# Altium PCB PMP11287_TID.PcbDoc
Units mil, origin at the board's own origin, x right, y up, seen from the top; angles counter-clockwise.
Board outline 2362.2 x 787.4 mil, 2 copper layers (Top Layer, Bottom Layer), stack 62 mil thick; 39 components, 23 nets, 88 pads, 34 vias.
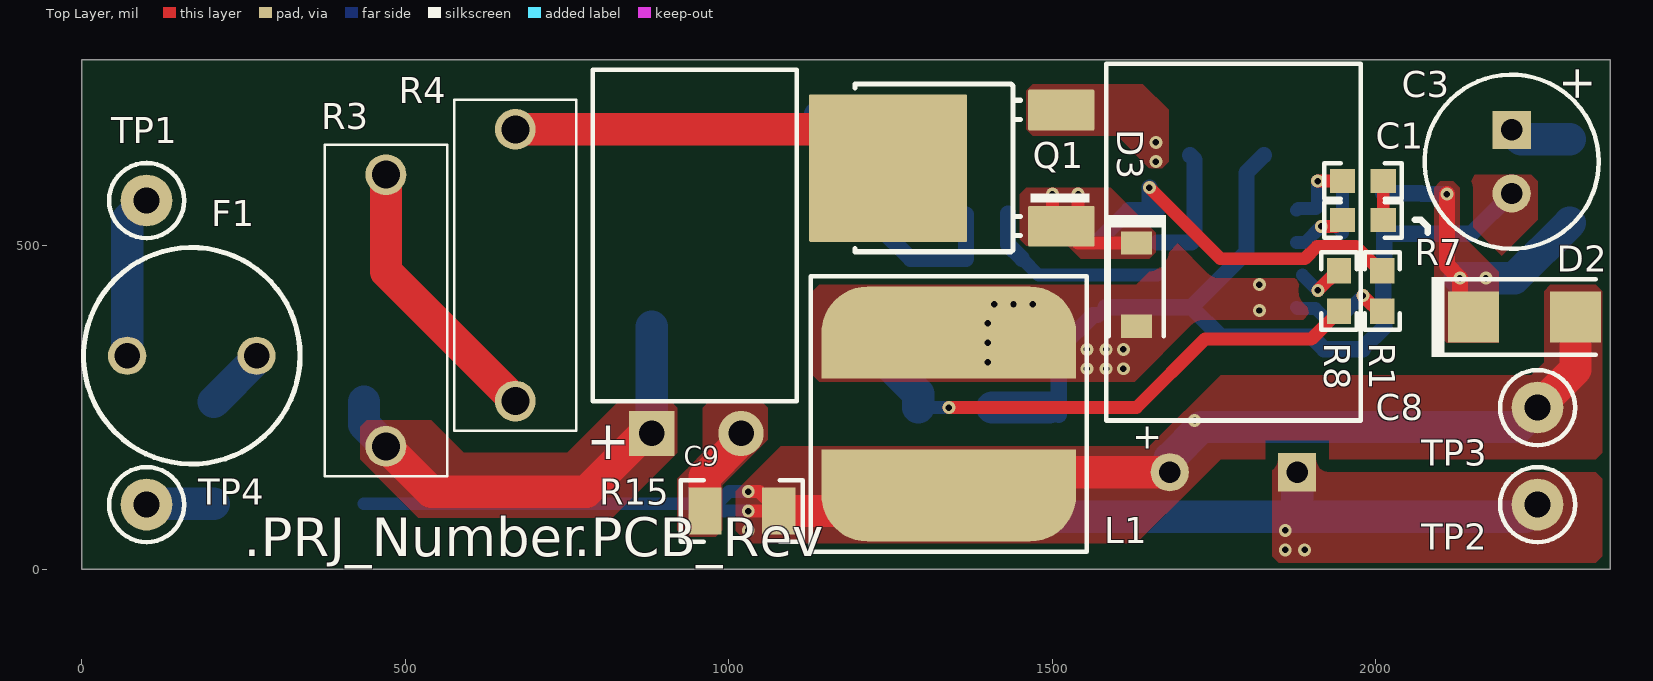
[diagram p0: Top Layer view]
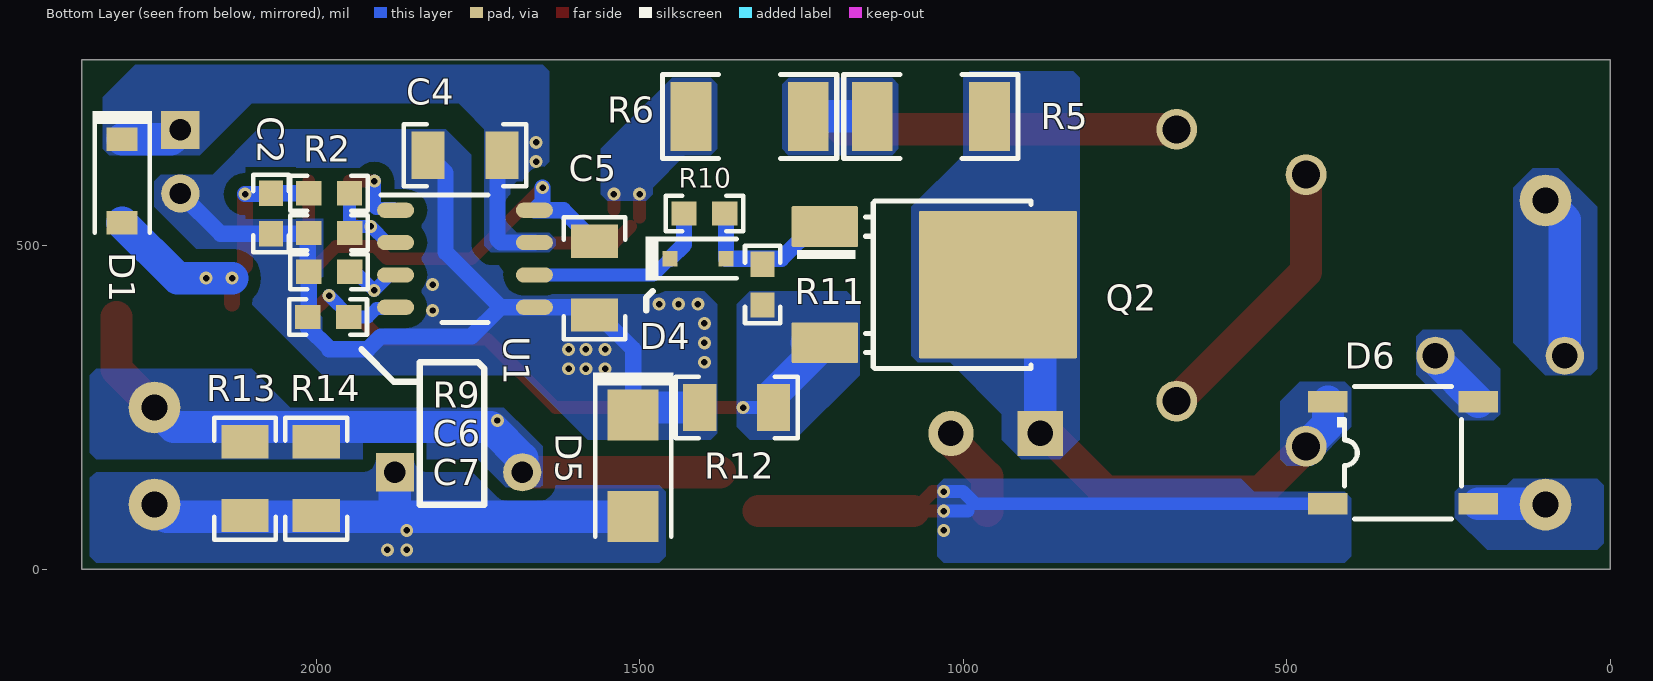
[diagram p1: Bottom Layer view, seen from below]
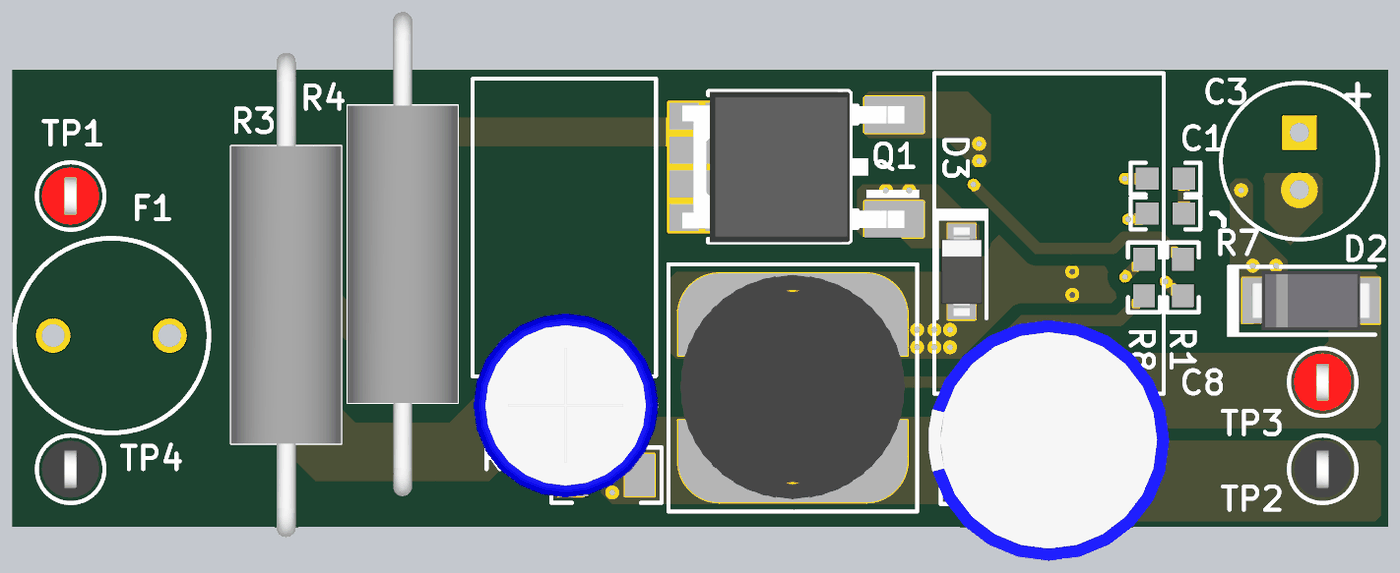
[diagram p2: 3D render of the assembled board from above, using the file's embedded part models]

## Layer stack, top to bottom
Top Solder: solder mask 0.4, Solder Resist, Dk 3.5
Top Layer: signal copper 1.4
Dielectric1: core 59.2, FR-4, Dk 4.8
Bottom Layer: signal copper 1.4
Bottom Solder: solder mask 0.4, Solder Resist, Dk 3.5

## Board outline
0,0 2362.2,0 2362.2,787.4 0,787.4

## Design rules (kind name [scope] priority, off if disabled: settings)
AcuteAngle [All] p1: minimum=4.50000000000000E+0001 checktracksonly=FALSE
AssemblyTestPointUsage [All] p1: valid=2
Clearance Clearance_1 [InNetClass('HV') vs InNet('GND')] p1: gap=60 ignorepadtopadclearanceinfootprint=FALSE except(0: Arc-Hole Track-Hole SMDPad-Hole THPad-Hole Via-Hole Fill-Hole Poly-Hole Region-Hole Text-Hole)
Clearance Clearance_Keepouts [((IsTrack Or IsArc) And Not InPoly) And IsFree and IsKeepOut vs ((IsTrack Or IsArc) And Not InPoly) And IsFree and IsKeepOut] p2: gap=0 ignorepadtopadclearanceinfootprint=FALSE
Clearance Clearance_BoardEdge_MountingHoles [OnCopper and InComponentClass('Mounting Holes') vs IsKeepOut] p3: gap=40 ignorepadtopadclearanceinfootprint=FALSE except(0: Arc-Hole Track-Hole SMDPad-Hole THPad-Hole Via-Hole Fill-Hole Poly-Hole Region-Hole Text-Hole)
Clearance Clearance_BoardEdge_Poly [OnCopper and InPoly vs IsKeepOut] p4: gap=25 ignorepadtopadclearanceinfootprint=FALSE except(0: Arc-Hole Track-Hole SMDPad-Hole THPad-Hole Via-Hole Fill-Hole Poly-Hole Region-Hole Text-Hole)
Clearance Clearance_BoardEdge [OnCopper and Not InComponentClass('Logo') and not InComponentClass('FiducialMark') and not InRegion(1000,500,4000,800) and Not IsKeepout vs IsKeepOut] p5: gap=75 ignorepadtopadclearanceinfootprint=FALSE except(0: Arc-Hole Track-Hole SMDPad-Hole THPad-Hole Via-Hole Fill-Hole Poly-Hole Region-Hole Text-Hole)
Clearance Clearance_Poly [InPolygon] p6: gap=20 ignorepadtopadclearanceinfootprint=FALSE except(0: Arc-Hole Track-Hole SMDPad-Hole THPad-Hole Via-Hole Fill-Hole Poly-Hole Region-Hole Text-Hole)
Clearance [All] p7: gap=7.87 ignorepadtopadclearanceinfootprint=FALSE except(0: Arc-Hole Track-Hole SMDPad-Hole THPad-Hole Via-Hole Fill-Hole Poly-Hole Region-Hole Text-Hole)
ComponentClearance ComponentClearance_MountingHoles_FiducialMarks [InComponentClass('Mounting Holes') vs InComponentClass('FiducialMark')] p1: gap=20 collisioncheckmode=3 verticalgap=10 showdistances=FALSE
ComponentClearance ComponentClearance_Shunt [InComponentClass('Header') vs InComponentClass('Shunt')] p2: gap=0 collisioncheckmode=3 verticalgap=0 showdistances=FALSE
ComponentClearance ComponentClearance_Logo [InComponentClass('Logo')] p3: gap=5 collisioncheckmode=3 verticalgap=10 showdistances=FALSE
ComponentClearance ComponentClearance_ScrewToNut [(HasFootprint('NY PMS 440 0025 PH')) vs (HasFootprint('Keystone_1902C'))] p4: gap=20 collisioncheckmode=3 verticalgap=100000 showdistances=FALSE
ComponentClearance ComponentClearance_MountingHoles [InComponentClass('Mounting Holes')] p5: gap=20 collisioncheckmode=3 verticalgap=10 showdistances=FALSE
ComponentClearance ComponentClearance_SmallPassives [HasFootprint('0201*') or HasFootprint('0402*') or HasFootprint('0508') or HasFootprint('0603*') or HasFootprint('0612') or HasFootprint('0805*') or HasFootprint('0815*') or HasFootprint('0830*') or HasFootprint('1206*') or HasFootprint('1210*') or HasFootprint('1808*') or HasFootprint('1812*') or HasFootprint('1825*') or HasFootprint('2010*') or HasFootprint('2220*') or HasFootprint('2225*') or HasFootprint('2512*') or HasFootprint('2728*') or HasFootprint('3518*') vs HasFootprint('0201*') or HasFootprint('0402*') or HasFootprint('0508') or HasFootprint('0603*') or HasFootprint('0612') or HasFootprint('0805*') or HasFootprint('0815*') or HasFootprint('0830*') or HasFootprint('1206*') or HasFootprint('1210*') or HasFootprint('1808*') or HasFootprint('1812*') or HasFootprint('1825*') or HasFootprint('2010*') or HasFootprint('2220*') or HasFootprint('2225*') or HasFootprint('2512*') or HasFootprint('2728*') or HasFootprint('3518*')] p6: gap=20 collisioncheckmode=3 verticalgap=20 showdistances=FALSE
ComponentClearance ComponentClearance_THtoSMT [IsThruComponent vs IsSMTComponent] p7: gap=10 collisioncheckmode=3 verticalgap=10 showdistances=FALSE
ComponentClearance ComponentClearance_THtoTH [IsThruComponent vs IsThruComponent] p8: gap=10 collisioncheckmode=3 verticalgap=10 showdistances=FALSE
ComponentClearance [All] p9: gap=10 collisioncheckmode=3 verticalgap=10 showdistances=FALSE
DiffPairsRouting [All] p1: maxlimit=100 minlimit=10 mostfreqgap=10 toplayer_minwidth=15 toplayer_maxwidth=15 toplayer_prefwidth=15 bottomlayer_minwidth=15 bottomlayer_maxwidth=15 bottomlayer_prefwidth=15 maxuncoupledlength=1000
FabricationTestPointUsage TestPointUsage [All] p1: valid=2 allowmultiple=FALSE
FabricationTestpoint Testpoint [All] p1: side=3 testpointundercomponent=TRUE minsize=40 maxsize=100 preferedsize=60 minholesize=0 maxholesize=40 preferedholesize=32 testpointgrid=1 allowsidetop=TRUE allowsidebottom=TRUE usegrid=TRUE gridtolerance=0.01
FanoutControl Fanout_LCC [IsLCC] p1: bgadir=Out bgaviamode=Centered fanoutstyle=Auto fanoutdirection=Alternating viagrid=1 // Fanout_LCC (Default Rule)
FanoutControl Fanout_BGA [IsBGA] p2: bgadir=Out bgaviamode=Centered fanoutstyle=Auto fanoutdirection=Alternating viagrid=1 // Fanout_BGA (Default Rule)
FanoutControl Fanout_Default [All] p4: bgadir=Out bgaviamode=Centered fanoutstyle=Auto fanoutdirection=Alternating viagrid=1 // Fanout_Default (Default Rule)
FanoutControl Fanout_Small [(CompPinCount < 5)] p5: bgadir=Out bgaviamode=Centered fanoutstyle=Auto fanoutdirection=OutThenIn viagrid=1 // Fanout_Small (Default Rule)
Height [All] p1: minheight=0 maxheight=3000 prefheight=500
HoleSize [All] p1: absolutevalues=TRUE maxlimit=251 minlimit=7 maxpercent=80.000 minpercent=20.000
MinimumAnnularRing MinimumAnnularRing_ThermalPadVias [IsVia and InAnyComponent] p1: minimumring=5.91
MinimumAnnularRing [All] p2: minimumring=5
MinimumSolderMaskSliver MinimumSolderMaskSliver_Logo [InComponentClass('Logo') vs InComponentClass('Logo')] p1: minsoldermaskwidth=0.7
MinimumSolderMaskSliver [All] p2: minsoldermaskwidth=2
PlaneConnect [All] p1: planeconnectstyle=Relief reliefexpansion=10 reliefentries=4 reliefconductorwidth=10 reliefairgap=10
PolygonConnect PolygonConnect_10 [All vs IsNamedPolygon('D6_3') Or  IsNamedPolygon('F1_2') Or  IsNamedPolygon('R5_1') Or  IsNamedPolygon('D6_4') Or  IsNamedPolygon('CS') Or  IsNamedPolygon('12V') Or  IsNamedPolygon('C9_1') Or  IsNamedPolygon('C3_1') Or  IsNamedPolygon('12V') Or  IsNamedPolygon('C3_1') Or  IsNamedPolygon('C9_2') Or  IsNamedPolygon('12V') Or  IsNamedPolygon('12V') Or  IsNamedPolygon('SW') Or  IsNamedPolygon('D3_1') Or  IsNamedPolygon('C3_1') Or  IsNamedPolygon('C2_1') Or  IsNamedPolygon('C9_1') Or  IsNamedPolygon('SW') Or  IsNamedPolygon('D3_1') Or  IsNamedPolygon('C9_1')] p1: connectstyle=Direct reliefconductorwidth=10 reliefentries=4 polygonreliefangle="90 Angle" airgapwidth=10
PolygonConnect PolygonConnect_9 [All vs IsNamedPolygon('C9_1') Or  IsNamedPolygon('D3_1') Or  IsNamedPolygon('C9_1') Or  IsNamedPolygon('CS') Or  IsNamedPolygon('C3_1') Or  IsNamedPolygon('C9_1') Or  IsNamedPolygon('R5_1') Or  IsNamedPolygon('D3_1') Or  IsNamedPolygon('C3_1') Or  IsNamedPolygon('D6_4') Or  IsNamedPolygon('D6_3') Or  IsNamedPolygon('F1_2') Or  IsNamedPolygon('C3_1') Or  IsNamedPolygon('C2_1') Or  IsNamedPolygon('SW')] p2: connectstyle=Direct reliefconductorwidth=10 reliefentries=4 polygonreliefangle="90 Angle" airgapwidth=10
PolygonConnect PolygonConnect_8 [All vs IsNamedPolygon('D6_3') Or  IsNamedPolygon('C9_1') Or  IsNamedPolygon('R5_1') Or  IsNamedPolygon('C3_1') Or  IsNamedPolygon('F1_2') Or  IsNamedPolygon('C9_1') Or  IsNamedPolygon('D6_4') Or  IsNamedPolygon('D3_1') Or  IsNamedPolygon('CS') Or  IsNamedPolygon('C9_1')] p3: connectstyle=Direct reliefconductorwidth=10 reliefentries=4 polygonreliefangle="90 Angle" airgapwidth=10
PolygonConnect PolygonConnect_7 [All vs IsNamedPolygon('C9_1') Or  IsNamedPolygon('CS') Or  IsNamedPolygon('F1_2') Or  IsNamedPolygon('R5_1') Or  IsNamedPolygon('D6_4') Or  IsNamedPolygon('C9_1') Or  IsNamedPolygon('C9_1') Or  IsNamedPolygon('D6_3')] p4: connectstyle=Direct reliefconductorwidth=10 reliefentries=4 polygonreliefangle="90 Angle" airgapwidth=10
PolygonConnect PolygonConnect_6 [All vs IsNamedPolygon('GND2') Or  IsNamedPolygon('SGND') Or  IsNamedPolygon('GND1') Or  IsNamedPolygon('C901_1') Or  IsNamedPolygon('SGND') Or  IsNamedPolygon('GND2') Or  IsNamedPolygon('GND1')] p5: connectstyle=Direct reliefconductorwidth=10 reliefentries=4 polygonreliefangle="90 Angle" airgapwidth=10
PolygonConnect PolygonConnect_5 [All vs IsNamedPolygon('GND1') Or  IsNamedPolygon('GND1')] p6: connectstyle=Direct reliefconductorwidth=10 reliefentries=4 polygonreliefangle="90 Angle" airgapwidth=10
PolygonConnect PolygonConnect_4 [All vs IsNamedPolygon('C21_1') Or  IsNamedPolygon('C5_1') Or  IsNamedPolygon('C12_2') Or  IsNamedPolygon('C2_2') Or  IsNamedPolygon('C13_1') Or  IsNamedPolygon('C28_1') Or  IsNamedPolygon('C6_1') Or  IsNamedPolygon('GND') Or  IsNamedPolygon('GND2') Or  IsNamedPolygon('C14_1') Or  IsNamedPolygon('C13_1') Or  IsNamedPolygon('Q1_3') Or  IsNamedPolygon('C14_1') Or  IsNamedPolygon('C5_1') Or  IsNamedPolygon('GND2') Or  IsNamedPolygon('C28_1') Or  IsNamedPolygon('D5_2') Or  IsNamedPolygon('D6_2') Or  IsNamedPolygon('D2_1') Or  IsNamedPolygon('C12_2') Or  IsNamedPolygon('D2_1') Or  IsNamedPolygon('C4_1') Or  IsNamedPolygon('C4_1') Or  IsNamedPolygon('C2_2') Or  IsNamedPolygon('GND') Or  IsNamedPolygon('C33_1') Or  IsNamedPolygon('C9_1')] p7: connectstyle=Direct reliefconductorwidth=10 reliefentries=4 polygonreliefangle="90 Angle" airgapwidth=10
PolygonConnect PolygonConnect_3 [All vs IsNamedPolygon('C28_1') Or  IsNamedPolygon('C12_2') Or  IsNamedPolygon('C28_1') Or  IsNamedPolygon('C9_1') Or  IsNamedPolygon('D5_2') Or  IsNamedPolygon('C12_2') Or  IsNamedPolygon('C2_2') Or  IsNamedPolygon('C14_1') Or  IsNamedPolygon('C4_1') Or  IsNamedPolygon('C14_1') Or  IsNamedPolygon('D6_2') Or  IsNamedPolygon('GND2') Or  IsNamedPolygon('Q1_3') Or  IsNamedPolygon('C5_1') Or  IsNamedPolygon('D2_1') Or  IsNamedPolygon('C4_1') Or  IsNamedPolygon('C13_1') Or  IsNamedPolygon('C5_1') Or  IsNamedPolygon('C13_1') Or  IsNamedPolygon('C33_1') Or  IsNamedPolygon('D2_1') Or  IsNamedPolygon('GND') Or  IsNamedPolygon('GND') Or  IsNamedPolygon('GND2') Or  IsNamedPolygon('C2_2') Or  IsNamedPolygon('C6_1') Or  IsNamedPolygon('C21_1')] p8: connectstyle=Direct reliefconductorwidth=10 reliefentries=4 polygonreliefangle="90 Angle" airgapwidth=10
PolygonConnect PolygonConnect_2 [All vs IsNamedPolygon('C21_1') Or  IsNamedPolygon('C4_1') Or  IsNamedPolygon('D5_2') Or  IsNamedPolygon('C5_1') Or  IsNamedPolygon('C14_1') Or  IsNamedPolygon('C13_1') Or  IsNamedPolygon('C4_1') Or  IsNamedPolygon('C33_1') Or  IsNamedPolygon('C12_2') Or  IsNamedPolygon('D2_1') Or  IsNamedPolygon('C2_2') Or  IsNamedPolygon('C28_1') Or  IsNamedPolygon('C12_2') Or  IsNamedPolygon('D2_1') Or  IsNamedPolygon('C5_1') Or  IsNamedPolygon('Q1_3') Or  IsNamedPolygon('GND') Or  IsNamedPolygon('D6_2') Or  IsNamedPolygon('C6_1') Or  IsNamedPolygon('C2_2') Or  IsNamedPolygon('C14_1') Or  IsNamedPolygon('C28_1') Or  IsNamedPolygon('C13_1') Or  IsNamedPolygon('C9_1') Or  IsNamedPolygon('GND')] p9: connectstyle=Direct reliefconductorwidth=10 reliefentries=4 polygonreliefangle="90 Angle" airgapwidth=10
PolygonConnect PolygonConnect_1 [All vs IsNamedPolygon('C28_1') Or  IsNamedPolygon('D5_2') Or  IsNamedPolygon('C5_1') Or  IsNamedPolygon('C5_1') Or  IsNamedPolygon('D2_1') Or  IsNamedPolygon('C21_1') Or  IsNamedPolygon('C9_1') Or  IsNamedPolygon('C4_1') Or  IsNamedPolygon('C14_1') Or  IsNamedPolygon('C28_1') Or  IsNamedPolygon('C6_1') Or  IsNamedPolygon('C12_2') Or  IsNamedPolygon('C33_1') Or  IsNamedPolygon('C4_1') Or  IsNamedPolygon('C13_1') Or  IsNamedPolygon('C12_2') Or  IsNamedPolygon('D6_2') Or  IsNamedPolygon('C2_2') Or  IsNamedPolygon('C14_1') Or  IsNamedPolygon('D2_1') Or  IsNamedPolygon('C2_2') Or  IsNamedPolygon('C13_1')] p10: connectstyle=Direct reliefconductorwidth=10 reliefentries=4 polygonreliefangle="90 Angle" airgapwidth=10
PolygonConnect [All] p11: connectstyle=Relief reliefconductorwidth=10 reliefentries=4 polygonreliefangle="90 Angle" airgapwidth=10
RoutingVias ThermalPadVias [IsVia and InAnyComponent] p1: holewidth=7.87 width=19.68 viastyle="Through Hole" minholewidth=7.87 minwidth=19.68 maxholewidth=12.99 maxwidth=23.62
RoutingVias [All] p2: holewidth=16 width=34 viastyle="Through Hole" minholewidth=7.87 minwidth=20 maxholewidth=40 maxwidth=65
SilkToBoardRegionClearance [Not ((IsComment or IsDesignator) And (Hide <> 'False')) and not InRegion(1000,500,4000,800)] p1:
SilkToSilkClearance SilkToSilkClearance_Pb-FreeLogo [(HasFootprint('Pb-Free_Overlay_Medium') OR HasFootprint('Pb-Free_Overlay_Small')) vs (HasFootprint('Pb-Free_Overlay_Medium') OR HasFootprint('Pb-Free_Overlay_Small'))] p1: silktosilkclearance=0
SilkToSilkClearance [All] p2: silktosilkclearance=1
SilkToSolderMaskClearance "Silk to Solder Mask Opening" [All] p1: minsilkscreentomaskgap=1 clearancetoexposedcopper=FALSE
SolderMaskExpansion [All] p1: expansion=1.97
Width [All] p1: maxlimit=100 minlimit=6 preferedwidth=10 checkconnectedcopper=TRUE
14 further rules are at their usual default settings.

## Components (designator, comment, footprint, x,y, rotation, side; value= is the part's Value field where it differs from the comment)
C1 "06031C103MAT2A" 0603 1980.02,600.03 r0 top
C2 "06033C104JAT2A" 0603 2070,550 r270 bottom
C3 "UVR1C470MDD1TD" SEPC_C9 2210,630 r270 top
C4 "12063C105KAT2A" 1206 1770,640 r0 bottom
C5 "GCM31MR71E105KA37L" 1206 1570,450 r270 bottom
C6 "GRM1885C1H221JA01D" 0603 1980,460 r0 bottom
C7 "GRM1885C1H331JA01D" 0603 1981.46,390 r0 bottom
C8 "UVK1C102MPD1TD" ZL_1000x1600 1780,150 r180 top
C9 "UVZ2G010MPD1TD" CAPPRD350W60D800H1100 950,210 r0 top
D1 "1N4148W-7-F" SOD-123 2300,600 r270 bottom
D2 "RS1J" SMA 2230,390 r0 top
D3 "MMSZ5242B-7-F" SOD-123 1630,440 r270 top
D4 "MMDL914-TP" sod-323 1410,480 r180 bottom
D5 "RS1J" SMA 1510,160 r270 bottom
D6 "MDB6S" MICRODIP_4 320,180 r180 bottom
F1 "37203150001" FUSE_372 170,330 r180 top
L1 "SDR1006-221KL" SDR1006 1340,240 r270 top
Q1 "AOD1N60" DPAK 1380,620 r180 top
Q2 "AOD1N60" DPAK 1080,440 r180 bottom
R1 "CRCW0603100KFKEA" 0603 2010,430 r90 top
R2 "CRCW06039K53FKEA" 0603 1980.02,581.33 r0 bottom
R3 "PNP300JR-73-75R" RESAD2032W80L1300D480 470,400 r90 top
R4 "PNP300JR-73-75R" RESAD2032W80L1300D480 670,470 r90 top
R5 "CRCW2010220KJNEF" 2010 1050,700 r180 bottom
R6 "CRCW2010220KJNEF" 2010 1330,700 r180 bottom
R7 "CRCW060310K0FKEA" 0603 1980.02,540.03 r180 top
R8 "CRCW0603511RFKEA" 0603 1943,430 r90 top
R9 "CRCW06032K49FKEA" 0603 1980,520 r180 bottom
R10 "CRCW060310R0FKEA" 0603 1400,550 r0 bottom
R11 "CRCW0603100KFKEA" 0603 1310,440 r270 bottom
R12 "CRCW12061R00FKEA" 1206 1350,250 r0 bottom
R13 "CRCW12065K10JNEA" 1206 2110,140 r270 bottom
R14 "CRCW12065K10JNEA" 1206 2000,140 r270 bottom
R15 "ERJ-8ENF33R0V" 1206 1020,90 r180 top
TP1 "5000" Keystone5000 100,570 r0 top
TP2 "5001" Keystone5001 2250,100 r0 top
TP3 "5000" Keystone5000 2250,250 r0 top
TP4 "5001" Keystone5001 100,100 r0 top
U1 "UCC2813D-3" D0008A_N 1770,480 r180 bottom

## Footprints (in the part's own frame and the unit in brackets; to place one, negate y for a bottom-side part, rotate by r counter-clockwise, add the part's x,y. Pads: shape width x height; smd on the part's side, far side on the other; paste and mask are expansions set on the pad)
0603 [mm] "0603 from SM-752 data"
  rect 1x0.95 smd: 1(-0.8,0) 2(0.8,0)
  silkscreen extent -1.52,-0.69 1.52,0.69, body extent -0.87,-0.47 0.87,0.47, height 1
1206 [mm] "1206 from SM-752 data"
  rect 1.3x1.85 smd: 1(-1.45,0) 2(1.45,0)
  silkscreen extent -2.4,-1.21 2.4,1.21, body extent -1.7,-0.9 1.7,0.9, height 1.35
2010 [mm] "Chip Capacitor, Body 5.08x2.54mm, IPC Medium Density"
  rect 1.6x2.7 smd: 1(-2.3,0) 2(2.3,0)
  silkscreen extent -3.42,-1.65 3.42,1.65, body extent -2.73,-1.45 2.73,1.45, height 1.66
CAPPRD350W60D800H1100 [mm] "Capacitor, Alum, 8x11mm"
  rect 1.78x1.78 hole 1: 1(-1.75,0)
  round 1.78 hole 1: 2(1.75,0)
  body extent -4.03,-4.03 4.03,4.02, height 11.79
D0008A_N [mm] "SOIC, 8-Leads, Body 4.9x3.9mm, Pitch 1.27mm, IPC Medium Density"
  oval 1.45x0.6 smd: 1(-2.725,1.905) 2(-2.725,0.635) 3(-2.725,-0.635) 4(-2.725,-1.905) 5(2.725,-1.905) 6(2.725,-0.635) 7(2.725,0.635) 8(2.725,1.905)
  silkscreen extent -3.3,-2.5 0.9,2.5, body extent -3,-2.45 3,2.45, height 1.63
DPAK [mm] "D-PAK, 3-Pads, Body 6.22x6.73mm (max), TO-252AA using nominal STEP model"
  rrect6% 2.6x1.6 smd: 1(-3.4,2.28) 3(-3.4,-2.28)
  rrect2% 6.2x5.8 smd paste-2.9: 4(3.4,0)
  silkscreen extent -4.5,-3.3 4.7,3.28, body extent -3.86,-3.29 5.84,3.29, height 2.48
FUSE_372 [mm] "LITTELFUSE"
  round 1.5 hole 1: 1(-2.54,0) 2(2.54,0)
  silkscreen extent -4.25,-4.25 4.25,4.25, body extent -4.25,-4.25 4.25,4.25, height 8
Keystone5000 [mil] "For Keystone 500x miniature loop terminals"
  round 80 hole 40: 1(0,0)
  silkscreen extent -58,-58 58,58, body extent -49,-49 49,49, height 182
Keystone5001 [mil] "For Keystone 500x miniature loop terminals"
  round 80 hole 40: 1(0,0)
  silkscreen extent -58,-58 58,58, body extent -49,-49 49,49, height 182
MICRODIP_4 [mm] "FAIRCHILD"
  rect 1.55x0.85 smd: 1(-2.95,2) 2(-2.95,-2) 3(2.95,-2) 4(2.95,2)
  silkscreen extent -2.6,-2.6 2.3,2.6, body extent -3.4,-2.57 3.4,2.57, height 1.45
RESAD2032W80L1300D480 [mm] "VISHAY"
  round 1.6 hole 1.1: 1(-5.334,0) 2(5.334,0)
  silkscreen extent -6.5,-2.4 6.5,2.4, body extent -10.57,-2.4 10.57,2.4, height 4.78
SDR1006 [mm] "Bourns recommended land pattern"
  oval 3.6x10 smd: 1(-3.2,0) 2(3.2,0)
  rect 2x2 smd: 1(-2.4,4) 1(-2.4,-4) 2(2.4,4) 2(2.4,-4)
  silkscreen extent -5.4,-5.43 5.4,5.43, body extent -4.9,-4.9 4.86,4.88, height 5.8
SEPC_C9 [mm] "PANASONIC"
  rect 1.5x1.5 hole 0.838: 1(-1.25,0)
  round 1.5 hole 0.838: 2(1.25,0)
  silkscreen extent -3.42,-3.42 3.42,3.42, body extent -3.4,-3.4 3.4,3.4, height 9.05
SMA [mm] "Molded Diode, 2-Leads, Body 4.3x2.6mm, IPC Medium Density, based on OnSemi component dimensions and land pattern"
  rect 2x2 smd: 1(-2,0) 2(2,0)
  silkscreen extent -3.66,-1.57 2.79,1.57, body extent -2.6,-1.3 2.6,1.3, height 2.42
SOD-123 [mm] "On Semi recommended land pattern"
  rect 0.915x1.22 smd: 1(-1.637,0) 2(1.637,0)
  silkscreen extent -2.74,-1.17 2.03,1.17, body extent -1.93,-0.9 1.93,0.9, height 1.35
sod-323 [mm] "NXP recommended land pattern"
  rect 0.6x0.6 smd paste-0.05: 1(-1.1,0) 2(1.1,0)
  silkscreen extent -2.06,-0.86 1.53,0.86, body extent -1.3,-0.67 1.3,0.68, height 1.1
ZL_1000x1600 [mm] "RUBYCON"
  rect 1.5x1.5 hole 0.85: 1(-2.5,0)
  round 1.5 hole 0.85: 2(2.5,0)
  body extent -5.2,-5.23 5.25,5.25, height 17.51

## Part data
C1: "CAP, CERM, 0.01 µF, 100 V, +/- 20%, X7R, 0603"
C2: "CAP, CERM, 0.1 µF, 25 V, +/- 5%, X7R, 0603"
C3: library part 6SEPC470MW, "CAP ALUM 47UF 20% 16V RADIAL"
C4: "CAP, CERM, 1uF, 25V, +/-10%, X7R, 1206"
C5: "CAP, CERM, 1 µF, 25 V, +/- 10%, X7R, AEC-Q200 Grade 1, 1206"
C6: "CAP, CERM, 220 pF, 50 V, +/- 5%, C0G/NP0, 0603"
C7: "CAP, CERM, 330 pF, 50 V, +/- 5%, C0G/NP0, 0603"
C8: library part 63ZL120MEFC10X16, "CAP ALUM 1000UF 20% 16V RADIAL"
C9: library part 400AX6R8M8x11, "CAP ALUM 1UF 20% 400V RADIAL"
D1: "Diode, Ultrafast, 100V, 0.15A, SOD-123"
D2 D5: library part RS1G-13-F, "DIODE GEN PURP 600V 1A SMA"
D3: "Diode, Zener, 12 V, 500 mW, SOD-123"
D4: "Diode, Switching, 100V, 0.2A, SOD-323"
D6: "Diode, Switching-Bridge, 600 V, 1 A, MICRODIP_4"
F1: "Fuse, 0.315 A, 250VAC/VDC, TH"
L1: "Inductor, Drum Core, Ferrite, 220 µH, 0.66 A, 0.73 ohm, SMD"
Q1 Q2: library part AOD3N50, "MOSFET N-CH 600V 1.3A TO252"
R1: "RES, 100 k, 1%, 0.1 W, 0603"
R2: "RES, 9.53 k, 1%, 0.1 W, 0603"
R3 R4: library part AC03000001009JAC00, "RES 75 OHM 3W 5% AXIAL"
R5 R6: "RES, 220 k, 5%, 0.75 W, 2010"
R7: "RES, 10.0k ohm, 1%, 0.1W, 0603"
R8: "RES, 511 ohm, 1%, 0.1W, 0603"
R9: "RES, 2.49k ohm, 1%, 0.1W, 0603"
R10: "RES, 10.0, 1%, 0.1 W, 0603"
R11: "RES, 100k ohm, 1%, 0.1W, 0603"
R12: "RES, 1.00, 1%, 0.25 W, 1206"
R13 R14: "RES, 5.1 k, 5%, 0.25 W, 1206"
R15: "RES, 33.0, 1%, 0.25 W, 1206"
TP1 TP3: "Test Point, Miniature, Red, TH"
TP2 TP4: "Test Point, Miniature, Black, TH"
U1: library part UCC2813QDR-3Q1, "IC REG CTRLR BST FLYBK PWM 8SOIC"

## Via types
v1: diameter 20, hole 10, Top Layer to Bottom Layer, 34 vias

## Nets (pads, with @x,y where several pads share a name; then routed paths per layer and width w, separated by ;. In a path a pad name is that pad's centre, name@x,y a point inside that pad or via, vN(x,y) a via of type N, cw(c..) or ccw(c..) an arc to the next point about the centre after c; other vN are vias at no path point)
12V: C8.2 D2.2 D6.2 L1.2 R13.1 R14.1 R15.1 TP3.1 | length 2077
  Top Layer w20: v1(1030,90) R15.1 1047.09,120 v1(1030,120)
  Top Layer w50: R15.1 L1.2@1315.98,90 ; L1.2@1375.98,150 C8.2 ; TP3.1 2308.74,308.74 D2.2
  Bottom Layer w20: D6.2 981.26,101.26 1000,120 v1(1030,120) ; 992.52,90 v1(1030,90)
  Bottom Layer w50: C8.2 1681.57,171.57 1730,220 2220,220 TP3.1
  other v1: 1030,60 1720,230
CS: Q2.3 R8.1 R11.2 R12.1 | length 872.4
  Top Layer w20: v1(1340,250) 1630,250 1735.67,355.67 1900.17,355.67 R8.1
  Bottom Layer w20: R12.1 v1(1340,250)
  Bottom Layer w50: Q2.3@1241.69,350.24 Q2.3 1292.91,271.18 R12.1
GND: C8.1 D5.2 R13.2 R14.2 TP2.1 | length 814.9
  Bottom Layer w50: D5.2 2231.26,81.26 TP2.1 ; 1878.43,82.83 C8.1
  other v1: 1860,30 1890,30 1860,60
NetC1_1: C1.1 U1.1 | length 113.3
  Top Layer w20: v1(1910,600) C1.1
  Bottom Layer w20: U1.1 1880.16,557.87 1907.87,557.87 1910,560 v1(1910,600)
NetC1_2: C1.2 R7.1 | length 60
  Top Layer w20: R7.1 C1.2
NetC2_1: C2.1 D1.2 D2.1 R2.2 | length 479.5
  Top Layer w25: v1(2110,580) 2110,470 v1(2130,450) D2.1@2130,411.26
  Bottom Layer w25: R2.2 2069.84,581.33 C2.1 ; C2.1@2071.5,580 v1(2110,580)
  Bottom Layer w50: v1(2130,450) v1(2170,450) 2214.47,450 D1.2
NetC3_1: C3.1 C4.1 D1.1 Q1.3 U1.7 | length 288.4
  Bottom Layer w25: U1.7 1715,505 1720,510 1720,632.91 C4.1
  Bottom Layer w50: C3.1 2224.74,664.47 D1.1
  other v1: 1660,630 1660,660
NetC5_1: C5.1 R1.2 U1.8 | length 581.8
  Top Layer w20: v1(1650,590) 1760,480 1890,480 1909.06,499.06 1969.49,499.06 2007.05,461.5 R1.2
  Bottom Layer w25: C5.1 1617.91,555 U1.8 1650,567.72 v1(1650,590)
NetC6_1: C6.1 R8.2 U1.3 | length 118.1
  Top Layer w20: v1(1910.5,431) R8.2@1941,461.5
  Bottom Layer w20: U1.3@1886.5,455 v1(1910.5,431) C6.1@1939.5,460
NetC7_1: C7.1 R1.1 U1.4 | length 170.4
  Top Layer w20: v1(1980,423) 2011.5,391.5 R1.1@2011.5,390
  Bottom Layer w20: U1.4 1879.16,403.13 1906.87,403.13 1920,390 C7.1 1949.96,392.96 v1(1980,423)
NetC9_1: C9.1 D6.1 Q2.4 R3.1 R5.2 | length 725.1
  Top Layer w50: R3.1 540,120 780,120 870,210 C9.1
  Bottom Layer w50: D6.1 436.14,223.86 R3.1 ; C9.1 Q2.4@881.1,374.96
NetC9_2: C9.2 R15.2 | length 143.2
  Top Layer w50: R15.2 962.91,142.91 1018.9,198.9 C9.2
NetD3_1: D3.1 Q1.1 R6.1 | length 186.3
  Top Layer w20: Q1.1@1500,544.09 v1(1500,580) ; Q1.1 1539.63,504.47 D3.1 ; Q1.1@1540,556.38 v1(1540,580)
NetD4_2: D4.2 Q2.1 R10.1 R11.1 | length 241.6
  Bottom Layer w25: Q2.1 1231.1,529.76 1280.87,480 D4.2 R10.1@1366.69,548.19
NetD6_3: D6.3 TP4.1 | length 102.6
  Bottom Layer w50: TP4.1@101.26,101.26 D6.3
NetD6_4: D6.4 F1.1 | length 98.7
  Bottom Layer w50: D6.4 270,324.88 F1.1
NetF1_2: F1.2 TP1.1 | length 252.4
  Bottom Layer w50: F1.2 70,540 TP1.1
NetQ1_4: Q1.4 R4.2 | length 516.1
  Top Layer w50: R4.2 Q1.4@1186.14,680
NetR2_1: R2.1 R7.2 R9.2 U1.2 | length 184.1
  Top Layer w20: v1(1915.67,530) 1938.49,530 R7.2
  Bottom Layer w20: U1.2 1890.67,505 v1(1915.67,530) 1938.5,530 R9.2 R2.1
NetR3_2: R3.2 R4.1 | length 432.8
  Top Layer w50: R3.2 470,460 R4.1
NetR5_1: R5.1 R6.2 | length 98.9
  Bottom Layer w50: R5.1 R6.2
OUT: D4.1 R10.2 U1.6 | length 298.8
  Bottom Layer w20: D4.1 1478.31,455 U1.6
  Bottom Layer w25: R10.2 1431.5,501.81 D4.1
SW: C2.2 C3.2 C4.2 C5.2 C6.2 C7.2 D3.2 D5.1 L1.1 R9.1 R12.2 U1.5 | length 1396.2
  Bottom Layer w25: D5.1 1510,340 1562.91,392.91 C5.2 ; C5.2@1582.09,405 U1.5 1715,405 ; C4.2 1800,612.91 1800,490 1715,405 ; C7.2@2011.5,391.46 C6.2 ; C7.2 2012.95,374.41 1980,341.46 1980,340 1920,340 1900,360 1760,360 1715,405 ; C6.2@2012.99,461.5 2012.99,518.5 C2.2 2147.72,518.5 C3.2 C3.2@2210,587.18
  Bottom Layer w50: R12.2 D5.1@1495.43,250
  other v1: 1553.58,310 1583.15,310 1610,310 1400,320 1553.58,340 1583.15,340 1610,340 1400,350 1400,380 1820,400 1410,410 1440,410 1470,410 1820,440

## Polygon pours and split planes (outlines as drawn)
GND on Bottom Layer "GND" (solid, pour order 42): 1470,10 1460,20 1460,50 1460,120 1470,130 1490,130 1700,130 1750,180 1950,180 2320,180 2350,150 2350,120 2350,20 2340,10 2320,10
12V on Bottom Layer "12V" (solid, remove dead copper, pour order 40): 410,120 400,110 400,100 400,50 400,20 410,10 430,10 1030,10 1040,20 1040,40 1040,130 1030,140 1020,140 570,140 550,120
12V on Bottom Layer "12V" (solid, remove dead copper, pour order 38): 1650,190 1670,210 1710,250 1720,250 2040,250 2100,310 2120,310 2340,310 2350,300 2350,220 2350,180 2340,170 2230,170 1750,170 1700,120 1660,120 1650,130
SW on Bottom Layer "SW" (solid, remove dead copper, pour order 30): 1390,200 1380,210 1380,230 1380,410 1400,430 1420,430 1550,430 1800,680 1850,680 2090,680 2160,610 2180,610 2240,610 2250,600 2250,560 1990,300 1844.5,300 1680,300 1580,200
NetC3_1 on Bottom Layer "C3_1" (solid, remove dead copper, pour order 24): 2320,640 2330,650 2330,680 2330,700 2330,730 2280,780 2260,780 1650,780 1640,770 1640,660 1650,650 1677.48,650 1730,650 1740,660 1740,680 1770,710 1780,720 1840,720 2100,720 2180,640
NetC3_1 on Bottom Layer "C3_1" (solid, remove dead copper, pour order 18): 1640,630 1660,610 1670,610 1680,600 1690,600 1700,590 1700,560 1700,530 1690,520 1670,520 1640,520 1630,510 1630,500 1640,490 1660,490 1720,490 1730,490 1740,500 1740,510 1740,604.57 1740,680 1730,690 1726.26,690 1660,690 1640,670
NetD3_1 on Bottom Layer "D3_1" (solid, remove dead copper, pour order 16): 1490,570 1480,580 1480,590 1430,640 1420,640 1390,640 1380,650 1380,660 1380,750 1390,760 1440,760 1450,760 1520,690 1560,650 1560,580 1550,570
NetR5_1 on Bottom Layer "R5_1" (solid, remove dead copper, pour order 14): 1100,750 1110,760 1269.92,760 1280,749.92 1280,730 1280,650 1270,640 1110,640 1100,650
CS on Bottom Layer "CS" (solid, remove dead copper, pour order 12): 1160,360 1160,380 1160,410 1180,430 1190,430 1330,430 1350,410 1350,350 1350,220 1330,200 1306.26,200 1300,200 1260,200 1160,300
NetC9_1 on Bottom Layer "C9_1" (solid, remove dead copper, pour order 10): 400,280 410,290 430,290 480,290 510,260 510,240 510,170 500,160 470,160 460,160 400,220
NetC9_1 on Bottom Layer "C9_1" (solid, remove dead copper, pour order 8): 910,170 920,180 940,200 940,220 940,240 1020,320 1070,320 1080,330 1080,370 1080,560 1000,640 1000,660 1000,760 990,770 970,770 830,770 820,760 820,720 820,200 850,170
NetD6_4 on Bottom Layer "D6_4" (solid, remove dead copper, pour order 4): 180,230 170,240 170,260 170,300 170,310 230,370 250,370 290,370 300,360 300,320 300,300.55 229.45,230
NetF1_2 on Bottom Layer "F1_2" (solid, remove dead copper, pour order 2): 40,300 30,300 20,310 20,330 20,560 80,620 110,620 120,620 150,590 150,440 150,350 100,300
NetD6_3 on Bottom Layer "D6_3" (solid, remove dead copper, pour order 0): 10,130 20,140 40,140 150,140 160,130 220,130 230,130 240,120 240,90 240,80 190,30 20,30 10,40
GND on Top Layer "GND" (solid, remove dead copper, pour order 44): 1850,180 1840,170 1840,160 1840,20 1850,10 1880,10 2340,10 2350,20 2350,140 2340,150
12V on Top Layer "12V" (solid, remove dead copper, pour order 36): 2350,430 2340,440 2330,440 2280,440 2270,440 2260,430 2260,410 2260,320 2240,300 1850,300 1760,300 1650,190 1650,180 1650,110 1660,100 1690,100 1700,110 1760,170 2035.43,170 2340,170 2350,180
12V on Top Layer "12V" (solid, remove dead copper, pour order 34): 1010,60 1030,40 1060,40 1330,40 1630,40 1720,130 1720,150 1720,170 1700,190 1680,190 1080,190 1010,120
NetC9_2 on Top Layer "C9_2" (solid, remove dead copper, pour order 32): 930,50 920,60 920,70 920,140 940,160 960,180 960,200 960,250 970,260 1000,260 1050,260 1060,250 1060,220 1060,200 1000,140 990,130 990,125.43 990,60 980,50
NetC2_1 on Top Layer "C2_1" (solid, remove dead copper, pour order 26): 2110,350 2100,360 2100,380 2090,390 2090,540 2090,590 2100,600 2120,600 2130,590 2130,550 2130,520 2190,460 2190,350
SW on Top Layer "SW" (solid, remove dead copper, pour order 27): 1140,440 1130,430 1130,300 1140,290 2000,290 2250,540 2250,560 2250,600 2240,610 2190,610 2130,610 2080,660 2070,670 1990,670 1860,670 1630,440
NetD3_1 on Top Layer "D3_1" (solid, remove dead copper, pour order 22): 1470,500 1460,500 1450,510 1450,521.46 1450,580 1460,590 1490,590 1590,590 1660,520 1660,510 1660,490 1650,480 1616.26,480 1543.74,480 1523.74,500
NetC3_1 on Top Layer "C3_1" (solid, remove dead copper, pour order 20): 1470,750 1460,740 1460,724.92 1460,695.39 1460,680 1470,670 1480,670 1600,670 1650,620 1670,620 1680,630 1680,700 1680,710 1640,750
NetC9_1 on Top Layer "C9_1" (solid, remove dead copper, pour order 6): 450,230 440,230 430,220 430,170 480,120 520,80 810,80 820,80 920,180 920,230 920,250 910,260 890,260 830,260 750,180 590,180 540,230

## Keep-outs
Keep-Out Layer:
  text ".Layer_Name" at 577,-858.49 h60

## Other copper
Top Layer:
  text ".Layer_Name" at 577,-858.49 h60
Bottom Layer:
  text ".Layer_Name" at 577,-858.49 h60

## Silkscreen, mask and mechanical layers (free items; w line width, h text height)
Top Overlay:
  lines w7.01: 790,260 1104.96,260 1104.96,771.81 790,771.81 790,260 ; 1583.15,230 1976.85,230 1976.85,781.18 1583.15,781.18 1583.15,230
  lines w10: 2060,540 2070,540 2080,530 2080,520
  text ".PRJ_Number" at 250,20 h60
  text ".PCB_Rev" at 760,20 h60
  text ".Layer_Name" at 577,-858.49 h60
Bottom Overlay:
  lines w10: 1480,430 1490,420 1490,400 ; 1840,290 1880,290 1930,340 ; 1740,100 1740,310 1750,320 1840,320 1840,100 1740,100
  text ".Layer_Name" at 577,-858.49 h60
Top Paste:
  text ".Layer_Name" at 577,-858.49 h60
Bottom Paste:
  text ".Layer_Name" at 577,-858.49 h60
Top Solder:
  text ".Layer_Name" at 577,-858.49 h60
  text ".Layer_Name" at 577,-858.49 h60
Bottom Solder:
  text ".Layer_Name" at 577,-858.49 h60
Drill Guide:
  text ".Layer_Name" at 577,-858.49 h60
M1 Board Outline:
  the board outline again, w7.01
  text ".Layer_Name" at 577,-858.49 h60
M2 Board Dimensions:
  rectangle: 125,-400 500,-275
  rectangle: 0,-275 125,-150
  lines w7: 0,-275 1000,-275 ; 125,-400 125,-150 ; 250,-400 250,-150 ; 500,-400 500,-150 ; 750,-400 750,-150 ; 0,-400 0,-150 1000,-150 1000,-400 0,-400
  text ".Layer_Name" at 577,-858.49 h60
M3 3D STEP Top:
  text ".Layer_Name" at 577,-858.49 h60
M4 3D STEP Bottom:
  text ".Layer_Name" at 577,-858.49 h60
M5 Assembly Top:
  lines w10: -292,-930.17 6308,-930.17 ; -292,-726.83 6310,-726.83 ; -292,-523.5 -292,-1133.5 3713,-1133.5 6310,-1133.5 6310,-523.5 -291.5,-523.5 -291.5,-1133.5 1284,-1133.5 ; 2173,-1133.5 2173,-523.5 ; 3440,-726.83 3440,-523.5 ; 4280,-726.83 4280,-523.5 ; 4902,-1140 4902,-937.17
  text "COMPONENTS MARKED 'DNP' SHOULD NOT BE POPULATED." at 1153.5,-318.5 h60
  text "ASSEMBLY VARIANT:" at 1153,-434 h60
  text ".VariantName" at 2189,-434 h60
  text "PCB VIEWED FROM TOP SIDE" at -228.5,-655.67 h60
  text "BOARD #:" at 2248,-655.67 h60
  text ".PRJ_Number" at 2793.5,-655.67 h60
  text "REV:" at 3638,-655.67 h60
  text ".PCB_Rev" at 3929.5,-655.67 h60
  text "SVN REV:" at 4476,-655.67 h60
  text ".VersionControl_RevNumber" at 4982,-655.67 h60
  text "TID #:" at 2248,-859 h60
  text ".TID" at 2793.5,-859 h60
  text "PLOT NAME =" at -228.5,-1064.34 h60
  text ".plot_File_Name" at 577,-1064.34 h60
  text "GENERATED    :" at 2250,-1064.34 h60
  text ".Print_Date" at 3119.5,-1064.34 h60
  text ".Print_Time" at 3848.5,-1064.34 h60
  text "TEXAS INSTRUMENTS" at 5113,-1064.34 h60
M6 Assembly Bottom:
  lines w10: -292.5,-727.33 6309.5,-727.33 ; -290.5,-930.67 6309.5,-930.67 ; 1115.5,-1140.5 1115.5,-937.67 ; 1737.5,-727.33 1737.5,-524 ; 2577.5,-727.33 2577.5,-524 ; 3844.5,-1134 3844.5,-524 ; 4733.5,-1134 6309,-1134 6309,-524 -292.5,-524 -292.5,-1134 2304.5,-1134 6309.5,-1134 6309.5,-524
  text "COMPONENTS MARKED 'DNP' SHOULD NOT BE POPULATED." at 6102,-318 h60
  text ".VariantName" at 5058,-434 h60
  text "ASSEMBLY VARIANT:" at 6097,-434 h60
  text ".VersionControl_RevNumber" at 1035.5,-656.17 h60
  text "SVN REV:" at 1541.5,-656.17 h60
  text ".PCB_Rev" at 2088,-656.17 h60
  text "REV:" at 2379.5,-656.17 h60
  text ".PRJ_Number" at 3224,-656.17 h60
  text "BOARD #:" at 3769.5,-656.17 h60
  text "PCB VIEWED FROM BOTTOM SIDE" at 6246,-656.17 h60
  text ".TID" at 3224,-859.5 h60
  text "TID #:" at 3769.5,-859.5 h60
  text "TEXAS INSTRUMENTS" at 904.5,-1064.84 h60
  text ".Print_Time" at 2169,-1064.84 h60
  text ".Print_Date" at 2898,-1064.84 h60
  text "GENERATED    :" at 3767.5,-1064.84 h60
  text ".plot_File_Name" at 5440.5,-1064.84 h60
  text "PLOT NAME =" at 6246,-1064.84 h60
M9 Title Sheet:
  drawing of 57 lines, arcs and shapes, not listed
  text "1" at 739.84,8036.5 h70
  text "2" at 3235.5,8036.5 h70
  text "3" at 5724.84,8036.5 h70
  text "4" at 8231.51,8036.5 h70
  text "5" at 10730.5,8036.5 h70
  text "6" at 13235.5,8036.5 h70
  text "A" at -416.5,6893.5 h70
  text "A" at 14383.5,6893.5 h70
  text "B" at -416.5,4513.5 h70
  text "B" at 14383.5,4513.5 h70
  text "C" at -416.5,2138.5 h70
  text "C" at 14383.5,2138.5 h70
  text "PROJECT TITLE:" at 11343.5,277.5 h45
  text ".PRJ_Title" at 11393.5,144.17 h70
  text "DESIGNED FOR:" at 11343.5,-23.5 h45
  text ".PRJ_Customer" at 11393.5,-163.5 h70
  text "D" at -416.5,-231.5 h70
  text "D" at 14383.5,-231.5 h70
  text "FILE NAME:" at 11343.5,-323.5 h45
  text ".PCB_File_Name_No_Path" at 11393.5,-443.5 h70
  text "Texas Instruments (TI) and/or its licensors do not warrant the accuracy or completeness of this specification" at 6374,-605.34 h45
  text "ENGINEER:" at 11343.5,-613.5 h45
  text "LAYOUT BY:" at 12848.5,-613.5 h45
  text "or any information contained therein. TI and/or its licensors do not warrant that this design will meet" at 6329.01,-718 h45
  text ".PRJ_Engineer" at 11393.5,-768.49 h70
  text ".PCB_Layout" at 12899,-768.49 h70
  text "the specifications, will be suitable for your application or fit for any particular purpose, or will operate in" at 6329.01,-830.67 h45
  text ".Layer_Name" at 577,-858.49 h60
  text "ALTIUM DESIGNER VERSION:" at 12848.5,-923.5 h45
  text "an implementation. TI and/or its licensors do not warrant that the design is production worthy. You should" at 6329.01,-943.33 h45
  text "completely validate and test your design implementation to confirm the system functionality for your application." at 6374,-1056 h45
  text ".print_Scale" at 11393.5,-1056.83 h70
  text ".Application_BuildNumber" at 12899,-1056.83 h70
  text "1" at 739.84,-1263.5 h70
  text "2" at 3235.5,-1263.5 h70
  text "3" at 5724.84,-1263.5 h70
  text "4" at 8231.51,-1263.5 h70
  text "5" at 10730.5,-1263.5 h70
  text "6" at 13235.5,-1263.5 h70
M10 Fab Notes:
  drawing of 185 lines, arcs and shapes, not listed
  text "DESIGN INFORMATION" at 12381.02,5910 h60
  text "MIN. TRACK WIDTH:" at 11736.46,5730 h60
  text "10" at 12832.7,5730 h60
  text "MIL" at 12987.46,5730 h60
  text "MIN. CLEARANCE:" at 11736.46,5598 h60
  text "0.2" at 12772.7,5598 h60
  text "mm" at 12987.46,5598 h60
  text "MIN. VIA PAD SIZE:" at 11736.46,5466 h60
  text "20" at 12802.71,5466 h60
  text "MIL" at 12987.46,5466 h60
  text "0.05mm (2MIL)" at 12431.46,5324.29 h60
  text "MINIMUM ANNULAR RING" at 11407.23,5320 h60
  text "EXTERNAL" at 13139.46,5320 h60
  text "PER" at 11607.23,5202 h60
  text "IPC-D-275 CLASS 2 LEVEL C" at 11827.23,5202 h60
  text "MIL, HOLES" at 13315.46,5089.71 h60
  text "+/-" at 12923,5089 h60
  text "+/-" at 13777,5089 h60
  text "REGISTRATION TOLERANCES:" at 11407.23,5084 h60
  text "METAL" at 12607,5084 h60
  text "5" at 13183.2,5084 h60
  text "3" at 14016.2,5084 h60
  text "MIL" at 14132.46,5084 h60
  text "MATERIAL:" at 11332.46,4874.54 h60
  text "FR-4 High Tg" at 12318.9,4734.21 h60
  text "FR-408" at 11753.46,4725.64 h60
  text "X" at 12165.46,4725.64 h60
  text "OTHER" at 13241.46,4725.64 h60
  text "62 MIL (1.6mm) +/-10%" at 12073.56,4562.92 h60
  text "THICKNESS:" at 11407.23,4558.64 h60
  text "X" at 11945.4,4558.64 h60
  text "OTHER" at 13358.46,4558.64 h60
  text "TOLERANCE:" at 11407.23,4400.64 h60
  text "X" at 12246.53,4400.64 h60
  text "ANSI IPC-6012 TYPE 3 CLASS 2" at 12433.48,4400.64 h60
  text "OTHER +/-" at 12433.46,4244.64 h60
  text "BOW & TWIST:" at 11407.23,4087.64 h60
  text "X" at 12246.53,4087.64 h60
  text "ANSI IPC-6012 TYPE 3 CLASS 2" at 12433.48,4087.64 h60
  text "OTHER +/-" at 12433.46,3929.13 h60
  text "DRILLING:" at 11332.46,3790.64 h60
  text "REFERENCE:" at 11407.23,3673.64 h60
  text "X" at 12055.46,3673.64 h60
  text "AS SHOWN" at 12242.46,3673.64 h60
  text "X" at 12956.46,3673.64 h60
  text "NC_DRILL FILES" at 13093.46,3673.64 h60
  text "PTH MIN COPPER THICKNESS:" at 11407.23,3515.64 h60
  text "X" at 12757.46,3515.64 h60
  text "1MIL" at 12894.46,3515.64 h60
  text "OTHER" at 13391.46,3515.64 h60
  text "BOARD FINISH:" at 11332.46,3356.64 h60
  text "SILKSCREEN:" at 11487.68,3238.64 h60
  text "X" at 12436.46,3238.64 h60
  text "TOP" at 12562.46,3238.64 h60
  text "X" at 12946.46,3238.64 h60
  text "BOTTOM" at 13073.46,3238.64 h60
  text "SILKSCREEN COLOR:" at 11487.68,3071.64 h60
  text "X" at 12435.42,3071.64 h60
  text "WHITE" at 12562.46,3071.64 h60
  text "OTHER" at 13073.46,3071.64 h60
  text "SOLDER RESIST COLOR:" at 11487.68,2901.64 h60
  text "X" at 12055.42,2742.44 h60
  text "GREEN" at 12182.46,2742.44 h60
  text "BLUE" at 12773.46,2742.44 h60
  text "OTHER" at 13311.46,2742.44 h60
  text "IMMERSION GOLD (ENIG)" at 12393.46,2553.92 h60
  text "ENEPIG" at 13731,2550.64 h60
  text "SURFACE FINISH:" at 11332.46,2549.64 h60
  text "IMM. TIN/SILVER OR EQUIV" at 11662,2392.64 h60
  text "OTHER" at 13093.46,2392.64 h60
  text "X" at 11500,2390 h60
  text "ARRAY/PANEL:" at 11332.46,2213.64 h60
  text "CUT AND TRIM PER MECH LAYER 1" at 12393.46,2209.35 h60
  text "N.C. ROUTE" at 12393.46,2057.64 h60
  text "X" at 13072.46,2057.64 h60
  text "V. SCORE" at 13259.46,2057.64 h60
  text "CERTIFICATION:" at 11332.46,1920.64 h60
  text "MATERIALS AND WORKMANSHIP FOR ALL PCBS" at 12057.46,1920.64 h60
  text "TO MEET OR EXCEED THE REQUIREMENTS OF:" at 12057.46,1822.64 h60
  text "X" at 11683.96,1686.13 h60
  text "ANSI IPC-A-600F CLASS ->" at 11822.96,1686.13 h60
  text "X" at 13462.02,1686.13 h60
  text "2" at 13580.96,1686.14 h60
  text "1" at 13265.96,1684.64 h60
  text "3" at 13934.96,1684.64 h60
  text "X" at 11686.02,1526.64 h60
  text "UL 94V-0" at 11822.96,1526.64 h60
  text "X" at 12498.02,1526.64 h60
  text "RoHS" at 12634.96,1526.64 h60
  text "OTHER" at 13279.36,1526.64 h60
  text "PER ORDER" at 13676.42,1526.64 h60
  text "ADDITIONAL REQUIREMENTS:" at 11332.46,1385.64 h60
  text "MICROSECTION:" at 11407.23,1270.64 h60
  text "YES" at 12312.96,1270.64 h60
  text "REQUIRED" at 13174.46,1114.49 h60
  text "BARE BOARD ELEC. TEST:" at 11407.23,1111.64 h60
  text "NONE" at 12712.96,1111.64 h60
  text "PER ORDER" at 13766.46,1111.64 h60
  text "X" at 12580,1110 h60
  text "MANUFACTURER'S UL:" at 11407.23,954.64 h60
  text "RAIL" at 12572.96,950.35 h60
  text "METAL" at 13064.77,950.35 h60
  text "X" at 13440,950 h60
  text "SILK" at 13576.46,950.35 h60
  text ".Layer_Name" at 577,-858.49 h60
M11 Gerber Information:
  lines w10: -292,-930.17 6308,-930.17 ; -292,-726.83 6310,-726.83 ; -292,-523.5 -292,-1133.5 3713,-1133.5 6310,-1133.5 6310,-523.5 -291.5,-523.5 -291.5,-1133.5 1284,-1133.5 ; 2173,-1133.5 2173,-523.5 ; 3440,-726.83 3440,-523.5 ; 4280,-726.83 4280,-523.5 ; 4902,-1140 4902,-937.17
  text "ALL ARTWORK VIEWED FROM TOP SIDE" at -228.5,-655.67 h60
  text "BOARD #:" at 2248,-655.67 h60
  text ".PRJ_Number" at 2793.5,-655.67 h60
  text "REV:" at 3638,-655.67 h60
  text ".PCB_Rev" at 3929.5,-655.67 h60
  text "SVN REV:" at 4476,-655.67 h60
  text ".VersionControl_RevNumber" at 4982,-655.67 h60
  text "LAYER NAME =" at -228.5,-858.49 h60
  text "TID #:" at 2248,-859 h60
  text ".TID" at 2793.5,-859 h60
  text "PLOT NAME =" at -228.5,-1064.34 h60
  text ".plot_File_Name" at 577,-1064.34 h60
  text "GENERATED    :" at 2250,-1064.34 h60
  text ".Print_Date" at 3119.5,-1064.34 h60
  text ".Print_Time" at 3848.5,-1064.34 h60
  text "TEXAS INSTRUMENTS" at 5113,-1064.34 h60
M12 Stackup:
  drawing of 191 lines, arcs and shapes, not listed
  text "Layer" at 9798.08,7830 h60
  text "Name" at 10207.99,7830 h60
  text "Material" at 11137.73,7830 h60
  text "Thickness" at 11997.5,7830 h60
  text "Constant" at 12647.34,7830 h60
  text "Board Layer Stack" at 13217.2,7830 h60
  text "1" at 9798.08,7710 h60
  text "Top Overlay" at 10207.99,7710 h60
  text "2" at 9798.08,7590 h60
  text "Top Solder" at 10207.99,7590 h60
  text "Solder Resist" at 11137.73,7590 h60
  text "0.40mil" at 11997.5,7590 h60
  text "3.5" at 12647.34,7590 h60
  text "3" at 9798.08,7470 h60
  text "Top Layer" at 10207.99,7470 h60
  text "Copper" at 11137.73,7470 h60
  text "1.40mil" at 11997.5,7470 h60
  text "4" at 9798.08,7350 h60
  text "Dielectric1" at 10207.99,7350 h60
  text "FR-4" at 11137.73,7350 h60
  text "59.20mil" at 11997.5,7350 h60
  text "4.8" at 12647.34,7350 h60
  text "5" at 9798.08,7230 h60
  text "Bottom Layer" at 10207.99,7230 h60
  text "Copper" at 11137.73,7230 h60
  text "1.40mil" at 11997.5,7230 h60
  text "6" at 9798.08,7110 h60
  text "Bottom Solder" at 10207.99,7110 h60
  text "Solder Resist" at 11137.73,7110 h60
  text "0.40mil" at 11997.5,7110 h60
  text "3.5" at 12647.34,7110 h60
  text "7" at 9798.08,6990 h60
  text "Bottom Overlay" at 10207.99,6990 h60
  text ".Layer_Name" at 577,-858.49 h60
M13 Component Bodies Top:
  text ".Layer_Name" at 577,-858.49 h60
M14 Component Bodies Bottom:
  text ".Layer_Name" at 577,-858.49 h60
M15 Courtyards Top:
  text ".Layer_Name" at 577,-858.49 h60
M16 Courtyards Bottom:
  text ".Layer_Name" at 577,-858.49 h60
Drill Drawing:
  lines w10: 5536.09,2672.31 5591.34,2672.31 5563.72,2617.06 5536.09,2672.31 ; 5536.09,2741.38 5536.09,2755.19 5549.9,2769 5536.09,2782.82 5536.09,2796.63 5549.9,2796.63 5563.72,2782.82 5577.53,2796.63 5591.34,2796.63 5591.34,2782.82 5577.53,2769 5591.34,2755.19 5591.34,2741.38 5577.53,2741.38 5563.72,2755.19 5549.9,2741.38 5536.09,2741.38 ; 5536.09,2879.51 5549.9,2879.51 5549.9,2865.7 5577.53,2865.7 5577.53,2879.51 5591.34,2879.51 5591.34,2907.14 5577.53,2907.14 5577.53,2920.95 5549.9,2920.95 5549.9,2907.14 5536.09,2907.14 5536.09,2879.51 ; 5536.09,3003.83 5549.9,3003.83 5563.72,2990.02 5577.53,3003.83 5591.34,3003.83 5577.53,3017.64 5591.34,3031.46 5577.53,3031.46 5563.72,3045.27 5549.9,3031.46 5536.09,3031.46 5549.9,3017.64 5536.09,3003.83 ; 5536.09,3114.34 5563.72,3128.15 5591.34,3114.34 5577.53,3141.96 5591.34,3169.59 5563.72,3155.78 5536.09,3169.59 5549.9,3141.96 5536.09,3114.34 ; 5536.09,3238.66 5591.34,3238.66 5591.34,3293.91 5536.09,3293.91 5536.09,3238.66
  lines w12: 5486,2579.76 7464.02,2579.76 ; 5486,3325.68 7464.02,3325.68 ; 5823.86,2455.44 5823.86,3450 ; 6155.86,2455.44 6155.86,3450 ; 6792.43,2455.44 6792.43,3450 ; 7051.57,2455.44 7051.57,3450 ; 5486,2455.44 7464.02,2455.44 7464.02,3450 5486,3450 5486,2455.44
  text "Symbol" at 5560.59,3362.98 h72
  text "Quantity" at 5861.16,3362.98 h72
  text "Finished Hole Size" at 6193.16,3362.98 h72
  text "Plated" at 6829.72,3362.98 h72
  text "Hole Type" at 7088.86,3362.98 h72
  text "34" at 5861.16,3238.66 h60
  text "10.00mil (0.254mm)" at 6193.16,3238.66 h60
  text "PTH" at 6829.72,3238.66 h60
  text "Round" at 7088.86,3238.66 h60
  text "2" at 5861.16,3114.34 h60
  text "33.00mil (0.838mm)" at 6193.16,3114.34 h60
  text "PTH" at 6829.72,3114.34 h60
  text "Round" at 7088.86,3114.34 h60
  text "2" at 5861.16,2990.02 h60
  text "33.47mil (0.850mm)" at 6193.16,2990.02 h60
  text "PTH" at 6829.72,2990.02 h60
  text "Round" at 7088.86,2990.02 h60
  text "4" at 5861.16,2865.7 h60
  text "39.37mil (1.000mm)" at 6193.16,2865.7 h60
  text "PTH" at 6829.72,2865.7 h60
  text "Round" at 7088.86,2865.7 h60
  text "4" at 5861.16,2741.38 h60
  text "40.00mil (1.016mm)" at 6193.16,2741.38 h60
  text "PTH" at 6829.72,2741.38 h60
  text "Round" at 7088.86,2741.38 h60
  text "4" at 5861.16,2617.06 h60
  text "43.31mil (1.100mm)" at 6193.16,2617.06 h60
  text "PTH" at 6829.72,2617.06 h60
  text "Round" at 7088.86,2617.06 h60
  text "50 Total" at 5861.16,2492.74 h60
  text ".Layer_Name" at 577,-858.49 h60

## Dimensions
0,0 to 2362.2,0 on M2 Board Dimensions
0,0 to 0,787.4 on M2 Board Dimensions
0,-400 to 1000,-400 on M2 Board Dimensions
